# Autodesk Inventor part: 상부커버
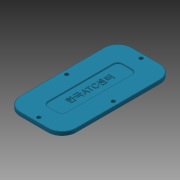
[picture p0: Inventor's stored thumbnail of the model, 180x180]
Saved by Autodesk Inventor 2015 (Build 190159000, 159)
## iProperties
Created: 2016-02
Part Number: 상부커버
Material: 강철, 연강
Document SubType Name: Modeling
Designer: mduedu
Density: 1 g/cm^3
Mass: 15.5198 g
Surface Area: 149.263 cm^2
Volume: 15.5198 cm^3
Appearance: 터키옥색
Author: mduedu
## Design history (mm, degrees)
sketch "스케치1"
  geometry: L1 (30, 60)-(-30, 60); L2 (-30, 60)-(-30, -60); L3 (-30, -60)-(30, -60); L4 (30, -60)-(30, 60); L5 (30, 60)-(-30, -60); L6 (-30, 60)-(30, -60); 1 further point
  constraints: 12 end point, 2 midpoint, 2 parallel, 1 horizontal, 1 perpendicular
  dimensions: "d0" = 60 distance of L2.end L3.end; "d2" = 120 distance of L1.end L2.end
extrude "돌출1" new body sketch "스케치1" distance "d3" = 4; taper "d4" = 0 deg
fillet "모깎기1" dims "d5" = 15
sketch "스케치2"
  geometry: L1 (30, 45)-(30, -45) reference; L2 (15, -60)-(-15, -60) reference; L3 (-30, -45)-(-30, 45) reference; L4 (-15, 60)-(15, 60) reference; L5 (25, 45)-(25, -45); L6 (15, -55)-(-15, -55); L7 (-25, -45)-(-25, 45); L8 (-15, 55)-(15, 55); A1 r 15 centre (15, 45) between (30, 45) and (15, 60) reference; A2 r 15 centre (15, -45) between (15, -60) and (30, -45) reference; A3 r 15 centre (-15, -45) between (-30, -45) and (-15, -60) reference; A4 r 15 centre (-15, 45) between (-15, 60) and (-30, 45) reference; A5 r 10 centre (15, 45) between (25, 45) and (15, 55); A6 r 10 centre (15, -45) between (15, -55) and (25, -45); A7 r 10 centre (-15, -45) between (-25, -45) and (-15, -55); A8 r 10 centre (-15, 45) between (-15, 55) and (-25, 45); 4 further points
  constraints: 8 end point, 8 point on circle, 4 centre point, 4 midpoint, 7 other
  dimensions: "d8" = 5 distance between parallel lines of L7 L3
hole "구멍1" sketch "스케치2" at (0, 55), (25, 0), (0, -55), (-25, 0) diameter "d9" = 4; stored, may be unused: countersink angle "d13" = 90 deg, drill point angle "d15" = 118 deg; dims "d10" = 6, "d11" = 4, "d12" = 2, "d14" = 8
sketch "스케치3"
  geometry: L1 (10, -40)-(-10, -40); L2 (-10, -40)-(-10, 40); L3 (-10, 40)-(10, 40); L4 (10, 40)-(10, -40); L5 (10, -40)-(-10, 40); L6 (-10, -40)-(10, 40); 1 further point
  constraints: 12 end point, 2 midpoint, 2 parallel, 1 horizontal, 1 perpendicular
  dimensions: "d16" = 80 distance of L1.end L2.end; "d18" = 20 distance of L2.end L3.end
extrude "돌출2" cut sketch "스케치3" distance "d19" = 1; taper "d20" = 0 deg
fillet "모깎기2" dims "d21" = 5
fillet "모깎기3" dims "d22" = 0.3
fillet "모깎기4" dims "d23" = 0.3
sketch "스케치4"
  geometry: 2 further points
  constraints: 1 coincident, 1 other
feature "엠보싱1" sketch "스케치4" dims "d0" = 60, "d2" = 120, "d11" = 4, "d24" = 0.5, "d25" = 0
node "솔리드1"
node "절단 모서리 투영1"
